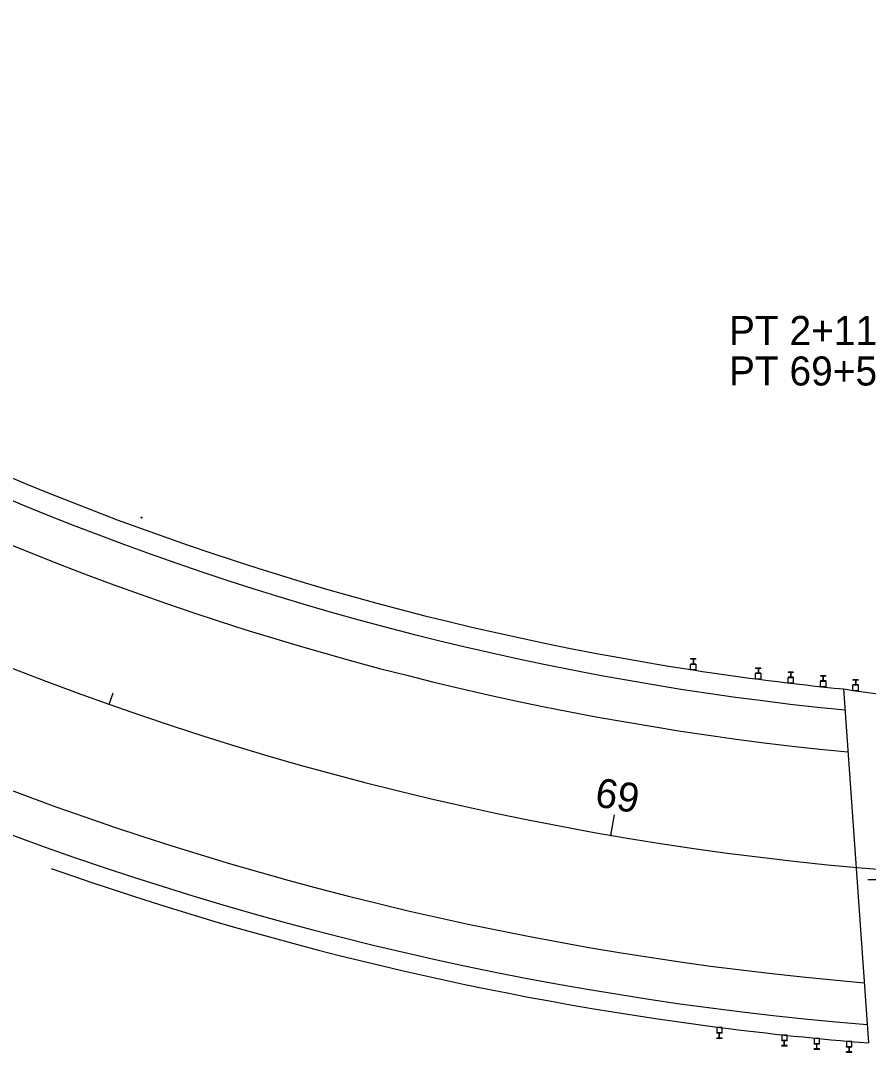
# Model space of a CAD drawing. Extents: x 27625 to 127752, y 6088 to 302357.
# Drawn here: x 27750.8 to 27832.4, y 6090 to 6189.4 of the extents above; entities that cross this region are included whole.
import ezdxf

# ---------------------------------------------------------------- set-up
doc = ezdxf.new("R2010")
doc.units = 0
for name, color, linetype in [('DR_X_Cells', 7, 'Continuous'), ('DV_X_Section_VMS_Line', 7, 'Continuous'), ('RS_Raster1', 7, 'Continuous'), ('RW_X_CL_100_Bearings', 7, 'Continuous'), ('RW_X_CL_100_Cardinal_Points', 7, 'Continuous'), ('RW_X_CL_100_Curve_Data', 7, 'Continuous'), ('RW_X_CL_100_Distances', 7, 'Continuous'), ('RW_X_CL_100_Stations', 7, 'Continuous'), ('SC_Scratch2', 7, 'Continuous'), ('SV_P_Control_Cells_Set', 7, 'Continuous'), ('SV_X_Random_Point', 7, 'Continuous'), ('SV_X_Shot_Marker', 7, 'Continuous'), ('UT_X_Telecom_Cells', 7, 'Continuous')]:
    doc.layers.add(name, color=color, linetype=linetype)

msp = doc.modelspace()

# ---------------------------------------------------------------- linework, layer by layer
at = {"layer": 'DR_X_Cells'}
for p, q in [((27759.332, 6123.553), (27759.732, 6124.684)), ((27807.655, 6110.944), (27807.994, 6112.915))]:
    msp.add_line(p, q, dxfattribs=at)
at = {"layer": 'DV_X_Section_VMS_Line'}
msp.add_line((27905.46, 6106.658), (27832.372, 6106.658), dxfattribs=at)
at = {"layer": 'RS_Raster1'}
for centre in [(27762.457, 6141.556), (27762.457, 6141.556), (27807.655, 6110.944)]:
    msp.add_circle(centre, 0.05, dxfattribs=at)
at = {"layer": 'RW_X_CL_100_Bearings'}
msp.add_line((27830.051, 6125.043), (27832.436, 6090.939), dxfattribs=at)
msp.add_arc((27849.042, 6249.077), 125.479, 261.29504, 268.22168, dxfattribs=at)
at = {"layer": 'RW_X_CL_100_Cardinal_Points'}
for p, q in [((27815.581, 6126.876), (27815.581, 6126.876)), ((27818.101, 6092.441), (27818.101, 6092.441))]:
    msp.add_line(p, q, dxfattribs=at)
for radius, start, end in [(278.276, 261.27765, 264.28123), (312.026, 262.69406, 265.34103)]:
    msp.add_arc((27857.78, 6401.934), radius, start, end, dxfattribs=at)
at = {"layer": 'RW_X_CL_100_Curve_Data'}
for p, q in [((27815.836, 6127.939), (27815.325, 6127.939)), ((27815.325, 6127.939), (27815.325, 6127.902)), ((27815.534, 6127.902), (27815.325, 6127.902)), ((27815.325, 6127.444), (27815.325, 6127.407)), ((27815.534, 6127.444), (27815.325, 6127.444)), ((27815.836, 6127.407), (27815.325, 6127.407)), ((27815.325, 6126.876), (27815.325, 6127.407)), ((27815.565, 6127.871), (27815.565, 6127.475)), ((27815.596, 6127.871), (27815.596, 6127.475)), ((27815.836, 6127.902), (27815.627, 6127.902)), ((27815.836, 6127.444), (27815.627, 6127.444)), ((27815.836, 6127.939), (27815.836, 6127.902)), ((27815.836, 6127.444), (27815.836, 6127.407)), ((27815.836, 6127.407), (27815.836, 6126.876)), ((27822.086, 6127.052), (27821.575, 6127.052)), ((27821.575, 6127.052), (27821.575, 6127.016)), ((27821.784, 6127.016), (27821.575, 6127.016)), ((27821.575, 6126.557), (27821.575, 6126.521)), ((27821.784, 6126.557), (27821.575, 6126.557)), ((27822.086, 6126.521), (27821.575, 6126.521)), ((27821.575, 6125.99), (27821.575, 6126.521)), ((27821.815, 6126.985), (27821.815, 6126.589)), ((27821.846, 6126.985), (27821.846, 6126.589)), ((27822.086, 6127.016), (27821.877, 6127.016)), ((27822.086, 6126.557), (27821.877, 6126.557)), ((27822.086, 6127.052), (27822.086, 6127.016)), ((27822.086, 6126.557), (27822.086, 6126.521)), ((27822.086, 6126.521), (27822.086, 6125.99)), ((27825.211, 6126.663), (27824.7, 6126.663)), ((27824.7, 6126.663), (27824.7, 6126.627)), ((27824.909, 6126.627), (27824.7, 6126.627)), ((27824.94, 6126.595), (27824.94, 6126.199)), ((27824.971, 6126.595), (27824.971, 6126.199)), ((27825.211, 6126.627), (27825.002, 6126.627)), ((27825.211, 6126.663), (27825.211, 6126.627)), ((27828.336, 6126.31), (27827.825, 6126.31)), ((27827.825, 6126.31), (27827.825, 6126.273)), ((27828.034, 6126.273), (27827.825, 6126.273)), ((27828.065, 6126.242), (27828.065, 6125.846)), ((27828.096, 6126.242), (27828.096, 6125.846)), ((27828.336, 6126.273), (27828.127, 6126.273)), ((27828.336, 6126.31), (27828.336, 6126.273)), ((27824.7, 6126.168), (27824.7, 6126.132)), ((27824.909, 6126.168), (27824.7, 6126.168)), ((27825.211, 6126.132), (27824.7, 6126.132)), ((27824.7, 6125.601), (27824.7, 6126.132)), ((27825.211, 6126.168), (27825.002, 6126.168)), ((27825.211, 6126.168), (27825.211, 6126.132)), ((27825.211, 6126.132), (27825.211, 6125.601)), ((27827.825, 6125.815), (27827.825, 6125.779)), ((27828.034, 6125.815), (27827.825, 6125.815)), ((27828.336, 6125.779), (27827.825, 6125.779)), ((27827.825, 6125.247), (27827.825, 6125.779)), ((27828.336, 6125.815), (27828.127, 6125.815)), ((27828.336, 6125.815), (27828.336, 6125.779)), ((27828.336, 6125.779), (27828.336, 6125.247)), ((27831.461, 6125.934), (27830.95, 6125.934)), ((27830.95, 6125.934), (27830.95, 6125.898)), ((27831.159, 6125.898), (27830.95, 6125.898)), ((27830.95, 6125.439), (27830.95, 6125.403)), ((27831.159, 6125.439), (27830.95, 6125.439)), ((27831.461, 6125.403), (27830.95, 6125.403)), ((27830.95, 6124.872), (27830.95, 6125.403)), ((27831.19, 6125.866), (27831.19, 6125.47)), ((27831.221, 6125.866), (27831.221, 6125.47)), ((27831.461, 6125.898), (27831.252, 6125.898)), ((27831.461, 6125.439), (27831.252, 6125.439)), ((27831.461, 6125.934), (27831.461, 6125.898)), ((27831.461, 6125.439), (27831.461, 6125.403)), ((27831.461, 6125.403), (27831.461, 6124.872)), ((27817.845, 6092.441), (27817.845, 6091.91)), ((27818.356, 6091.91), (27818.356, 6092.441)), ((27818.356, 6091.91), (27817.845, 6091.91)), ((27817.845, 6091.874), (27817.845, 6091.91)), ((27818.054, 6091.874), (27817.845, 6091.874)), ((27818.085, 6091.446), (27818.085, 6091.842)), ((27818.116, 6091.446), (27818.116, 6091.842)), ((27818.356, 6091.874), (27818.147, 6091.874)), ((27818.356, 6091.874), (27818.356, 6091.91)), ((27824.095, 6091.704), (27824.095, 6091.173)), ((27824.606, 6091.173), (27824.606, 6091.704)), ((27817.845, 6091.379), (27817.845, 6091.415)), ((27818.054, 6091.415), (27817.845, 6091.415)), ((27818.356, 6091.379), (27817.845, 6091.379)), ((27818.356, 6091.415), (27818.147, 6091.415)), ((27818.356, 6091.379), (27818.356, 6091.415)), ((27824.606, 6091.173), (27824.095, 6091.173)), ((27824.095, 6091.136), (27824.095, 6091.173)), ((27824.304, 6091.136), (27824.095, 6091.136)), ((27824.095, 6090.642), (27824.095, 6090.678)), ((27824.304, 6090.678), (27824.095, 6090.678)), ((27824.606, 6090.642), (27824.095, 6090.642)), ((27824.335, 6090.709), (27824.335, 6091.105)), ((27824.366, 6090.709), (27824.366, 6091.105)), ((27824.606, 6091.136), (27824.397, 6091.136)), ((27824.606, 6090.678), (27824.397, 6090.678)), ((27824.606, 6091.136), (27824.606, 6091.173)), ((27824.606, 6090.642), (27824.606, 6090.678)), ((27827.22, 6091.383), (27827.22, 6090.852)), ((27827.731, 6090.852), (27827.22, 6090.852)), ((27827.22, 6090.815), (27827.22, 6090.852)), ((27827.429, 6090.815), (27827.22, 6090.815)), ((27827.46, 6090.388), (27827.46, 6090.784)), ((27827.491, 6090.388), (27827.491, 6090.784)), ((27827.731, 6090.815), (27827.522, 6090.815)), ((27827.731, 6090.852), (27827.731, 6091.383)), ((27827.731, 6090.815), (27827.731, 6090.852)), ((27830.345, 6091.094), (27830.345, 6090.563)), ((27830.856, 6090.563), (27830.345, 6090.563)), ((27830.345, 6090.526), (27830.345, 6090.563)), ((27830.554, 6090.526), (27830.345, 6090.526)), ((27830.585, 6090.099), (27830.585, 6090.495)), ((27830.616, 6090.099), (27830.616, 6090.495)), ((27830.856, 6090.526), (27830.647, 6090.526)), ((27830.856, 6090.563), (27830.856, 6091.094)), ((27830.856, 6090.526), (27830.856, 6090.563)), ((27827.22, 6090.321), (27827.22, 6090.357)), ((27827.429, 6090.357), (27827.22, 6090.357)), ((27827.731, 6090.321), (27827.22, 6090.321)), ((27827.731, 6090.357), (27827.522, 6090.357)), ((27827.731, 6090.321), (27827.731, 6090.357)), ((27830.345, 6090.032), (27830.345, 6090.068)), ((27830.554, 6090.068), (27830.345, 6090.068)), ((27830.856, 6090.032), (27830.345, 6090.032)), ((27830.856, 6090.068), (27830.647, 6090.068)), ((27830.856, 6090.032), (27830.856, 6090.068))]:
    msp.add_line(p, q, dxfattribs=at)
for centre, start, end in [((27815.534, 6127.871), 0, 90), ((27815.534, 6127.475), 270, 0), ((27815.627, 6127.871), 90, 180), ((27815.627, 6127.475), 180, 270), ((27821.784, 6126.985), 0, 90), ((27821.784, 6126.589), 270, 0), ((27821.877, 6126.985), 90, 180), ((27821.877, 6126.589), 180, 270), ((27824.909, 6126.595), 0, 90), ((27825.002, 6126.595), 90, 180), ((27828.034, 6126.242), 0, 90), ((27828.127, 6126.242), 90, 180), ((27824.909, 6126.199), 270, 0), ((27825.002, 6126.199), 180, 270), ((27828.034, 6125.846), 270, 0), ((27828.127, 6125.846), 180, 270), ((27831.159, 6125.866), 0, 90), ((27831.159, 6125.47), 270, 0), ((27831.252, 6125.866), 90, 180), ((27831.252, 6125.47), 180, 270), ((27818.054, 6091.842), 360, 90), ((27818.054, 6091.447), 270, 360), ((27818.147, 6091.842), 90, 180), ((27818.147, 6091.447), 180, 270), ((27824.304, 6091.105), 360, 90), ((27824.304, 6090.709), 270, 360), ((27824.397, 6091.105), 90, 180), ((27824.397, 6090.709), 180, 270), ((27827.429, 6090.784), 360, 90), ((27827.522, 6090.784), 90, 180), ((27830.554, 6090.495), 360, 90), ((27830.647, 6090.495), 90, 180), ((27827.429, 6090.388), 270, 360), ((27827.522, 6090.388), 180, 270), ((27830.554, 6090.099), 270, 360), ((27830.647, 6090.099), 180, 270)]:
    msp.add_arc(centre, 0.0312, start, end, dxfattribs=at)
at = {"layer": 'RW_X_CL_100_Distances'}
msp.add_arc((27857.817, 6402.088), 312.184, 250.52724, 262.69097, dxfattribs=at)
at = {"layer": 'RW_X_CL_100_Stations'}
for p, q in [((27815.836, 6126.876), (27815.325, 6126.876)), ((27822.086, 6125.99), (27821.575, 6125.99)), ((27825.211, 6125.601), (27824.7, 6125.601)), ((27828.336, 6125.247), (27827.825, 6125.247)), ((27831.461, 6124.872), (27830.95, 6124.872)), ((27818.356, 6092.441), (27817.845, 6092.441)), ((27824.606, 6091.704), (27824.095, 6091.704)), ((27827.731, 6091.383), (27827.22, 6091.383)), ((27830.856, 6091.094), (27830.345, 6091.094))]:
    msp.add_line(p, q, dxfattribs=at)
at = {"layer": 'SV_P_Control_Cells_Set'}
msp.add_arc((27857.773, 6401.919), 278.26, 229.7841, 261.27856, dxfattribs=at)
at = {"layer": 'SV_X_Random_Point'}
for radius, end in [(280.276, 264.35125), (310.276, 265.29182)]:
    msp.add_arc((27857.78, 6401.934), radius, 229.785, end, dxfattribs=at)
at = {"layer": 'SV_X_Shot_Marker'}
msp.add_arc((27857.78, 6401.934), 295.276, 229.785, 270, dxfattribs=at)
msp.add_arc((27857.78, 6401.934), 295.276, 229.785, 270, dxfattribs=at)
at = {"layer": 'UT_X_Telecom_Cells'}
for radius, end in [(284.276, 264.48829), (306.276, 265.17719)]:
    msp.add_arc((27857.78, 6401.934), radius, 229.785, end, dxfattribs=at)

# ---------------------------------------------------------------- texts
at = {"layer": 'DR_X_Cells'}
msp.add_text('69', height=2.8, rotation=350.22622, dxfattribs=at).set_placement((27806.001, 6113.765))
at = {"layer": 'SC_Scratch2'}
for s, p in [('PT 2+118.472 METERS', (27819.019, 6158.183)), ('PT 69+50.37 STATIONS', (27819.019, 6154.282))]:
    msp.add_text(s, height=2.8, dxfattribs=at).set_placement(p)

doc.saveas('drawing.dxf')
